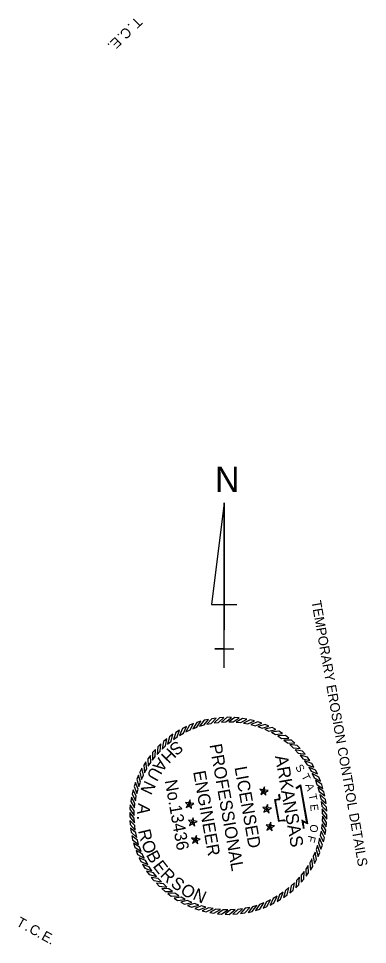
# Model space of a CAD drawing. Extents: x 979995 to 981206, y 1838837 to 1840486.
# Drawn here: x 980994 to 981206, y 1838948 to 1839509 of the extents above; entities that cross this region are included whole.
import ezdxf

# ---------------------------------------------------------------- set-up
doc = ezdxf.new("R2010")
doc.units = 0
for name, color, linetype in [('1', 7, 'Continuous'), ('63', 7, 'Continuous'), ('G-ANNO-SYMB', 7, 'Continuous'), ('R_Draft', 7, 'Continuous')]:
    doc.layers.add(name, color=color, linetype=linetype)

msp = doc.modelspace()

# ---------------------------------------------------------------- linework, layer by layer
at = {"layer": '63'}
for p, q in [((981118.92, 1839215.5), (981111.23, 1839153.96)), ((981118.92, 1839115.5), (981118.92, 1839215.5)), ((981118.92, 1839215.5), (981118.92, 1839138.58)), ((981111.23, 1839153.96), (981126.61, 1839153.96)), ((981118.92, 1839115.5), (981118.92, 1839138.58)), ((981118.92, 1839127.04), (981113.15, 1839127.04)), ((981113.15, 1839127.04), (981124.69, 1839127.04)), ((981118.92, 1839115.5), (981118.92, 1839127.04))]:
    msp.add_line(p, q, dxfattribs=at)
at = {"layer": 'G-ANNO-SYMB'}
for points in [[(981100.3, 1839081.73), (981097.92, 1839080.77), (981095.74, 1839076.75), (981098.24, 1839077.94)], [(981104.75, 1839083.2), (981102.3, 1839082.44), (981099.81, 1839078.6), (981102.4, 1839079.59)], [(981109.29, 1839084.33), (981106.79, 1839083.76), (981104.01, 1839080.13), (981106.67, 1839080.91)], [(981113.92, 1839085.09), (981111.38, 1839084.72), (981108.32, 1839081.32), (981111.03, 1839081.89)], [(981118.58, 1839085.49), (981116.02, 1839085.32), (981112.71, 1839082.17), (981115.46, 1839082.52)], [(981123.27, 1839085.52), (981120.7, 1839085.55), (981117.15, 1839082.67), (981119.92, 1839082.81)], [(981127.94, 1839085.19), (981125.39, 1839085.42), (981121.62, 1839082.83), (981124.39, 1839082.74)], [(981132.57, 1839084.48), (981130.04, 1839084.91), (981126.08, 1839082.63), (981128.84, 1839082.33)], [(981137.13, 1839083.42), (981134.65, 1839084.05), (981130.52, 1839082.08), (981133.24, 1839081.57)], [(981141.6, 1839082), (981139.17, 1839082.82), (981134.9, 1839081.19), (981137.57, 1839080.46)], [(981145.94, 1839080.24), (981143.58, 1839081.25), (981139.2, 1839079.95), (981141.81, 1839079.02)], [(981091.83, 1839077.75), (981089.62, 1839076.43), (981088.1, 1839072.12), (981090.39, 1839073.68)], [(981095.99, 1839079.9), (981093.69, 1839078.76), (981091.83, 1839074.59), (981094.23, 1839075.96)], [(981150.13, 1839078.14), (981147.85, 1839079.33), (981143.38, 1839078.38), (981145.91, 1839077.25)], [(981154.14, 1839075.72), (981151.97, 1839077.09), (981147.43, 1839076.49), (981149.86, 1839075.16)], [(981084.08, 1839072.49), (981082.11, 1839070.85), (981081.28, 1839066.35), (981083.29, 1839068.26)], [(981087.85, 1839075.27), (981085.76, 1839073.79), (981084.57, 1839069.37), (981086.73, 1839071.11)], [(981157.95, 1839072.99), (981155.89, 1839074.53), (981151.32, 1839074.29), (981153.64, 1839072.77)], [(981161.53, 1839069.98), (981159.6, 1839071.66), (981155.03, 1839071.78), (981157.22, 1839070.09)], [(981077.25, 1839066.09), (981075.56, 1839064.16), (981075.44, 1839059.59), (981077.13, 1839061.78)], [(981080.54, 1839069.43), (981078.7, 1839067.63), (981078.22, 1839063.09), (981080.09, 1839065.14)], [(981164.86, 1839066.69), (981163.07, 1839068.52), (981158.52, 1839069), (981160.58, 1839067.14)], [(981167.93, 1839063.15), (981166.29, 1839065.11), (981161.79, 1839065.95), (981163.69, 1839063.93)], [(981074.23, 1839062.51), (981072.7, 1839060.45), (981072.94, 1839055.89), (981074.45, 1839058.21)], [(981170.71, 1839059.37), (981169.22, 1839061.47), (981164.81, 1839062.65), (981166.54, 1839060.49)], [(981173.18, 1839055.4), (981171.87, 1839057.6), (981167.56, 1839059.13), (981169.12, 1839056.84)], [(981069.08, 1839054.69), (981067.89, 1839052.42), (981068.84, 1839047.95), (981069.98, 1839050.47)], [(981071.5, 1839058.7), (981070.14, 1839056.53), (981070.73, 1839052), (981072.06, 1839054.43)], [(981175.34, 1839051.24), (981174.2, 1839053.54), (981170.02, 1839055.4), (981171.4, 1839052.99)], [(981066.98, 1839050.5), (981065.97, 1839048.14), (981067.27, 1839043.76), (981068.21, 1839046.37)], [(981177.16, 1839046.92), (981176.2, 1839049.3), (981172.19, 1839051.48), (981173.37, 1839048.98)], [(981065.22, 1839046.16), (981064.4, 1839043.73), (981066.04, 1839039.46), (981066.76, 1839042.14)], [(981142.83, 1839040.76), (981142.34, 1839041.68), (981140.38, 1839041.96), (981141.8, 1839040.58)], [(981142.83, 1839040.76), (981143.55, 1839041.51), (981143.21, 1839043.46), (981142.34, 1839041.68)], [(981178.64, 1839042.48), (981177.87, 1839044.92), (981174.04, 1839047.42), (981175.02, 1839044.82)], [(981179.76, 1839037.93), (981179.19, 1839040.43), (981175.56, 1839043.21), (981176.34, 1839040.55)], [(981062.74, 1839037.14), (981062.31, 1839034.61), (981064.6, 1839030.65), (981064.89, 1839033.4)], [(981063.8, 1839041.7), (981063.18, 1839039.21), (981065.14, 1839035.08), (981065.66, 1839037.81)], [(981142.83, 1839040.76), (981141.8, 1839040.58), (981140.94, 1839038.8), (981142.69, 1839039.73)], [(981142.83, 1839040.76), (981142.69, 1839039.73), (981144.11, 1839038.35), (981143.77, 1839040.31)], [(981142.83, 1839040.76), (981143.77, 1839040.31), (981145.52, 1839041.24), (981143.55, 1839041.51)], [(981180.53, 1839033.31), (981180.15, 1839035.85), (981176.75, 1839038.91), (981177.32, 1839036.19)], [(981062.04, 1839032.51), (981061.81, 1839029.95), (981064.4, 1839026.18), (981064.48, 1839028.95)], [(981097.84, 1839032.83), (981097.35, 1839033.75), (981095.39, 1839034.03), (981096.82, 1839032.65)], [(981097.84, 1839032.83), (981096.82, 1839032.65), (981095.95, 1839030.87), (981097.7, 1839031.8)], [(981097.84, 1839032.83), (981098.57, 1839033.58), (981098.22, 1839035.53), (981097.35, 1839033.75)], [(981097.84, 1839032.83), (981097.7, 1839031.8), (981099.12, 1839030.42), (981098.78, 1839032.37)], [(981097.84, 1839032.83), (981098.78, 1839032.37), (981100.53, 1839033.3), (981098.57, 1839033.58)], [(981144.72, 1839030.02), (981144.24, 1839030.94), (981142.27, 1839031.21), (981143.7, 1839029.84)], [(981144.72, 1839030.02), (981145.45, 1839030.77), (981145.1, 1839032.72), (981144.24, 1839030.94)], [(981144.72, 1839030.02), (981145.66, 1839029.56), (981147.41, 1839030.49), (981145.45, 1839030.77)], [(981180.93, 1839028.64), (981180.75, 1839031.2), (981177.6, 1839034.52), (981177.96, 1839031.77)], [(981061.7, 1839027.83), (981061.67, 1839025.27), (981064.55, 1839021.71), (981064.41, 1839024.48)], [(981144.72, 1839030.02), (981143.7, 1839029.84), (981142.83, 1839028.06), (981144.58, 1839028.99)], [(981144.72, 1839030.02), (981144.58, 1839028.99), (981146.01, 1839027.61), (981145.66, 1839029.56)], [(981180.96, 1839023.96), (981180.99, 1839026.52), (981178.11, 1839030.07), (981178.24, 1839027.31)], [(981180.62, 1839019.28), (981180.85, 1839021.84), (981178.26, 1839025.61), (981178.18, 1839022.84)], [(981061.73, 1839023.15), (981061.91, 1839020.59), (981065.05, 1839017.27), (981064.7, 1839020.02)], [(981099.74, 1839022.09), (981099.25, 1839023.01), (981097.29, 1839023.28), (981098.71, 1839021.91)], [(981099.74, 1839022.09), (981098.71, 1839021.91), (981097.84, 1839020.12), (981099.59, 1839021.06)], [(981099.74, 1839022.09), (981100.46, 1839022.84), (981100.12, 1839024.79), (981099.25, 1839023.01)], [(981099.74, 1839022.09), (981099.59, 1839021.06), (981101.02, 1839019.68), (981100.67, 1839021.63)], [(981099.74, 1839022.09), (981100.67, 1839021.63), (981102.42, 1839022.56), (981100.46, 1839022.84)], [(981146.62, 1839019.28), (981146.13, 1839020.2), (981144.17, 1839020.47), (981145.59, 1839019.1)], [(981146.62, 1839019.28), (981147.34, 1839020.03), (981147, 1839021.98), (981146.13, 1839020.2)], [(981146.62, 1839019.28), (981147.56, 1839018.82), (981149.31, 1839019.75), (981147.34, 1839020.03)], [(981179.92, 1839014.65), (981180.35, 1839017.18), (981178.06, 1839021.14), (981177.76, 1839018.39)], [(981062.13, 1839018.48), (981062.51, 1839015.94), (981065.9, 1839012.88), (981065.34, 1839015.6)], [(981062.9, 1839013.86), (981063.47, 1839011.36), (981067.1, 1839008.57), (981066.32, 1839011.23)], [(981101.63, 1839011.34), (981102.35, 1839012.09), (981102.01, 1839014.04), (981101.14, 1839012.26)], [(981146.62, 1839019.28), (981145.59, 1839019.1), (981144.72, 1839017.31), (981146.47, 1839018.24)], [(981146.62, 1839019.28), (981146.47, 1839018.24), (981147.9, 1839016.87), (981147.56, 1839018.82)], [(981178.86, 1839010.09), (981179.48, 1839012.58), (981177.51, 1839016.7), (981177, 1839013.98)], [(981064.02, 1839009.31), (981064.79, 1839006.86), (981068.62, 1839004.37), (981067.64, 1839006.96)], [(981101.63, 1839011.34), (981101.14, 1839012.26), (981099.18, 1839012.54), (981100.61, 1839011.16)], [(981101.63, 1839011.34), (981100.61, 1839011.16), (981099.74, 1839009.38), (981101.49, 1839010.31)], [(981101.63, 1839011.34), (981101.49, 1839010.31), (981102.91, 1839008.94), (981102.57, 1839010.89)], [(981101.63, 1839011.34), (981102.57, 1839010.89), (981104.32, 1839011.82), (981102.35, 1839012.09)], [(981177.44, 1839005.62), (981178.26, 1839008.06), (981176.62, 1839012.32), (981175.89, 1839009.65)], [(981065.5, 1839004.87), (981066.45, 1839002.49), (981070.47, 1839000.3), (981069.29, 1839002.81)], [(981173.58, 1838997.1), (981174.77, 1838999.37), (981173.82, 1839003.84), (981172.68, 1839001.31)], [(981175.68, 1839001.28), (981176.68, 1839003.64), (981175.39, 1839008.03), (981174.45, 1839005.42)], [(981067.32, 1839000.55), (981068.46, 1838998.25), (981072.64, 1838996.39), (981071.26, 1838998.8)], [(981171.16, 1838993.09), (981172.52, 1838995.26), (981171.93, 1838999.79), (981170.59, 1838997.36)], [(981069.48, 1838996.39), (981070.79, 1838994.19), (981075.1, 1838992.66), (981073.54, 1838994.95)], [(981071.95, 1838992.41), (981073.43, 1838990.32), (981077.85, 1838989.14), (981076.11, 1838991.3)], [(981165.41, 1838985.69), (981167.1, 1838987.63), (981167.22, 1838992.2), (981165.52, 1838990)], [(981168.43, 1838989.28), (981169.96, 1838991.34), (981169.72, 1838995.9), (981168.2, 1838993.58)], [(981074.73, 1838988.64), (981076.37, 1838986.67), (981080.87, 1838985.84), (981078.97, 1838987.86)], [(981162.12, 1838982.36), (981163.96, 1838984.15), (981164.43, 1838988.7), (981162.57, 1838986.65)], [(981077.8, 1838985.1), (981079.59, 1838983.27), (981084.14, 1838982.79), (981082.08, 1838984.65)], [(981081.13, 1838981.81), (981083.06, 1838980.12), (981087.63, 1838980), (981085.44, 1838981.7)], [(981154.81, 1838976.51), (981156.9, 1838978), (981158.08, 1838982.42), (981155.93, 1838980.68)], [(981158.58, 1838979.29), (981160.55, 1838980.94), (981161.38, 1838985.43), (981159.37, 1838983.53)], [(981084.71, 1838978.79), (981086.77, 1838977.26), (981091.34, 1838977.5), (981089.02, 1838979.02)], [(981088.52, 1838976.07), (981090.69, 1838974.7), (981095.23, 1838975.3), (981092.8, 1838976.63)], [(981142.36, 1838970.06), (981144.74, 1838971.02), (981146.92, 1838975.04), (981144.41, 1838973.85)], [(981146.67, 1838971.89), (981148.97, 1838973.02), (981150.83, 1838977.2), (981148.43, 1838975.82)], [(981150.83, 1838974.04), (981153.03, 1838975.36), (981154.56, 1838979.67), (981152.27, 1838978.1)], [(981092.53, 1838973.65), (981094.8, 1838972.46), (981099.28, 1838973.41), (981096.75, 1838974.54)], [(981096.72, 1838971.55), (981099.08, 1838970.54), (981103.46, 1838971.84), (981100.85, 1838972.77)], [(981101.06, 1838969.78), (981103.49, 1838968.96), (981107.76, 1838970.6), (981105.08, 1838971.33)], [(981105.52, 1838968.37), (981108.01, 1838967.74), (981112.14, 1838969.71), (981109.42, 1838970.22)], [(981110.09, 1838967.3), (981112.62, 1838966.87), (981116.58, 1838969.16), (981113.82, 1838969.46)], [(981114.72, 1838966.6), (981117.27, 1838966.37), (981121.04, 1838968.96), (981118.27, 1838969.04)], [(981119.39, 1838966.27), (981121.96, 1838966.24), (981125.51, 1838969.12), (981122.74, 1838968.98)], [(981124.07, 1838966.3), (981126.63, 1838966.47), (981129.95, 1838969.62), (981127.2, 1838969.27)], [(981128.74, 1838966.7), (981131.28, 1838967.07), (981134.34, 1838970.47), (981131.63, 1838969.9)], [(981133.36, 1838967.46), (981135.87, 1838968.03), (981138.65, 1838971.66), (981135.99, 1838970.88)], [(981137.91, 1838968.59), (981140.36, 1838969.35), (981142.85, 1838973.19), (981140.26, 1838972.2)]]:
    msp.add_lwpolyline(points, close=True, dxfattribs=at)
for points in [[(981162.31, 1839042.83), (981165.04, 1839044.72), (981169.23, 1839021.02), (981166.39, 1839022.56), (981166.7, 1839020.96), (981166.95, 1839019.62), (981167.04, 1839018.25)], [(981162.53, 1839042.51), (981164.76, 1839044.07), (981168.72, 1839021.74), (981165.87, 1839023.28), (981166.32, 1839020.89), (981166.57, 1839019.57), (981166.66, 1839018.22)], [(981155.66, 1839022.48), (981155.26, 1839022.83), (981154.74, 1839022.87), (981153.49, 1839022.79), (981151.85, 1839022.5), (981149.52, 1839035.73), (981151.73, 1839036.12), (981152.22, 1839036.21), (981152.29, 1839036.77), (981151.96, 1839038.66), (981152.41, 1839039.08)], [(981155.91, 1839022.77), (981155.42, 1839023.19), (981154.75, 1839023.26), (981153.45, 1839023.17), (981152.16, 1839022.94), (981149.96, 1839035.42), (981151.8, 1839035.75), (981152.57, 1839035.88), (981152.68, 1839036.78), (981152.37, 1839038.52), (981152.67, 1839038.8)]]:
    msp.add_lwpolyline(points, dxfattribs=at)

# ---------------------------------------------------------------- texts
at = {"layer": '1'}
msp.add_text('TEMPORARY EROSION CONTROL DETAILS', height=5.8625, rotation=280, dxfattribs=at).set_placement((981171.63, 1839155.79))
at = {"layer": '63'}
msp.add_text('N', height=15.38, rotation=0, dxfattribs=at).set_placement((981113.29, 1839221.91))
at = {"layer": 'G-ANNO-SYMB'}
for s, height, rotation, p in [('S', 7.5, 218.1636, (981090.27, 1839071.88)), ('H', 7.5, 225.619, (981085.08, 1839067.49)), ('PROFESSIONAL', 7.5, 280, (981109.95, 1839068.86)), ('A', 7.5, 233.4472, (981079.16, 1839061.61)), ('ARKANSAS', 7.747, 280, (981149.58, 1839061.97)), ('U', 7.5, 240.9026, (981075.16, 1839056.16)), ('LICENSED', 7.5, 280, (981125.09, 1839055.21)), ('S', 4.75, 299.7726, (981161.69, 1839055.44)), ('No.13436', 7.47, 280, (981082.88, 1839047.17)), ('ENGINEER', 7.5, 280, (981100.07, 1839052.61)), ('T', 4.75, 296.9015, (981165.41, 1839049.97)), ('N', 7.5, 244.9326, (981070.97, 1839047.75)), ('A', 4.75, 288.6788, (981167.89, 1839044.55)), ('T', 4.75, 281.4789, (981169.88, 1839038.68)), ('A', 7.5, 263.0991, (981066.91, 1839033.75)), ('E', 4.75, 276.672, (981170.8, 1839032.67)), ('.', 7.5, 271.3, (981066.03, 1839026.12)), ('O', 4.75, 261.2218, (981171.19, 1839021.04)), ('R', 7.5, 283.2287, (981066.7, 1839016.89)), ('O', 7.5, 291.4296, (981068.51, 1839009.42)), ('F', 4.75, 255.3628, (981169.84, 1839014.31)), ('B', 7.5, 298.885, (981071.38, 1839002.29)), ('E', 7.5, 307.8315, (981075.36, 1838995.3)), ('R', 7.5, 315.6597, (981079.73, 1838989.64)), ('S', 7.5, 323.4878, (981085.95, 1838983.73)), ('O', 7.5, 324.7757, (981091.75, 1838979.52)), ('N', 7.5, 336.1007, (981099.3, 1838975.57))]:
    msp.add_text(s, height=height, rotation=rotation, dxfattribs=at).set_placement(p)
at = {"layer": 'R_Draft'}
for s, rotation, p in [('T', 224.0932, (981065.66, 1839510.16)), ('C', 224.0932, (981059.35, 1839504.05)), ('.', 224.0932, (981061.45, 1839506.08)), ('E', 224.0932, (981053.17, 1839498.06)), ('.', 224.0932, (981055.28, 1839500.1)), ('.', 224.0932, (981049.3, 1839494.31)), ('T', 330.9256, (980992.6, 1838959.79)), ('C', 330.9256, (981000.28, 1838955.52)), ('.', 330.9256, (980997.72, 1838956.94)), ('.', 330.9256, (981005.23, 1838952.77)), ('E', 330.9256, (981007.79, 1838951.34)), ('.', 330.9256, (981012.5, 1838948.73))]:
    msp.add_text(s, height=6, rotation=rotation, dxfattribs=at).set_placement(p)

doc.saveas('drawing.dxf')
